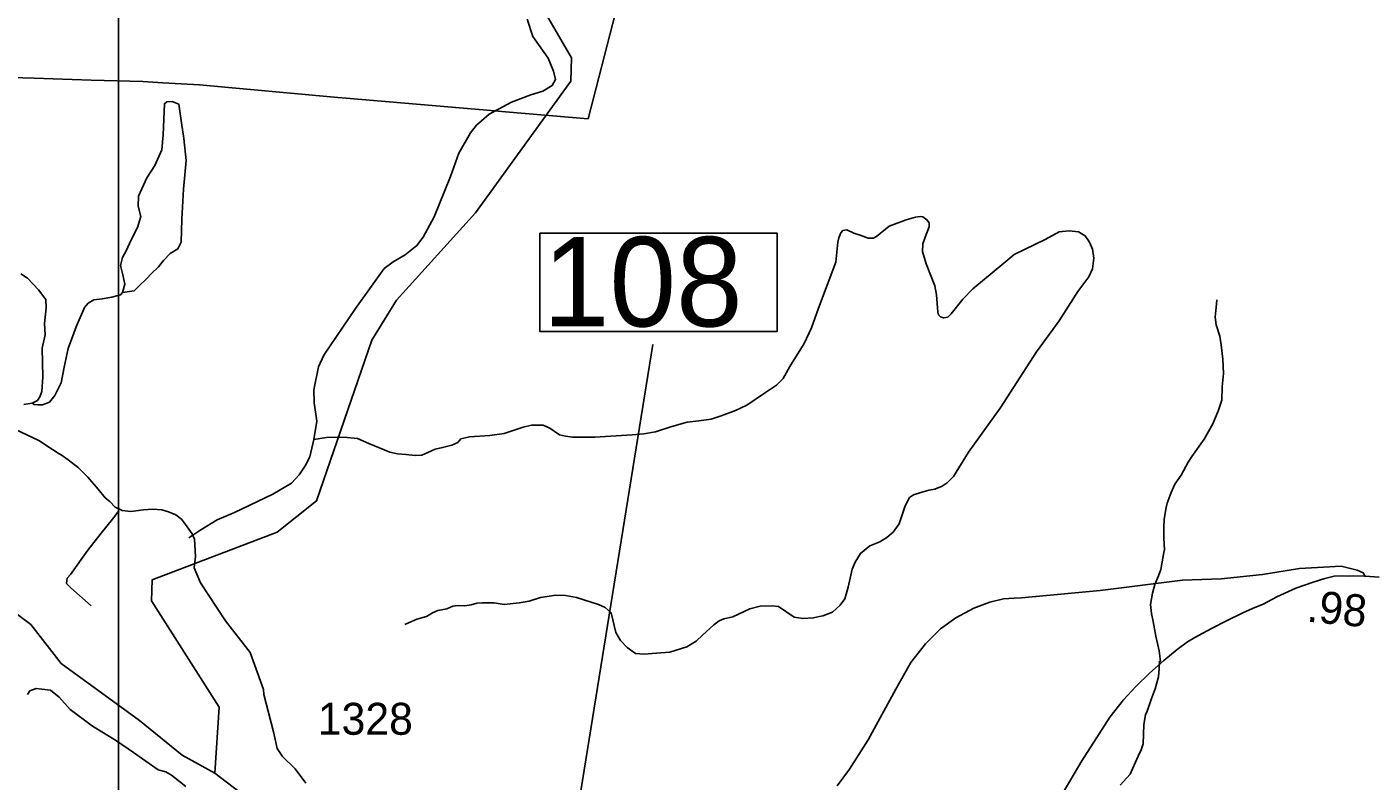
# Model space of a CAD drawing. Extents: x 1159738 to 1321356, y 736314 to 882035.
# Drawn here: x 1193750 to 1199006, y 794392 to 797342 of the extents above; entities that cross this region are included whole.
import ezdxf

# ---------------------------------------------------------------- set-up
doc = ezdxf.new("R2010")
doc.units = 0
for name, color, linetype in [('Exist Boundary Land Use Forest National US Forest Service', 7, 'Continuous'), ('Exist Hydrographic Creek Single Shore', 7, 'Continuous'), ('Exist Hydrographic Misc Water Feature', 7, 'Continuous'), ('Exist Road Non-System Type 51', 7, 'Continuous'), ('Exist Road Secondary Mileage Hundredths English Label', 7, 'Continuous'), ('Exist Road Secondary Structure Standard Bridge Number Label', 7, 'Continuous'), ('Exist Road Secondary Type 51 Attributed', 7, 'Continuous'), ('Exist Road Secondary Type 51 Number Label', 7, 'Continuous'), ('Map Preparation Inset Cut Line', 7, 'Continuous')]:
    doc.layers.add(name, color=color, linetype=linetype)

msp = doc.modelspace()

# ---------------------------------------------------------------- linework, layer by layer
at = {"layer": 'Exist Boundary Land Use Forest National US Forest Service'}
msp.add_lwpolyline([(1192585.3, 797430.1), (1192612.2, 797313), (1192647.2, 797232), (1192653.7, 797233.3), (1193021.2, 797300.1), (1193010.2, 797169), (1193647.2, 797145), (1193779.1, 797141.1), (1194001.2, 797134.2), (1194203.2, 797128.1), (1194281.5, 797123.9), (1194425.2, 797116.1), (1194966.2, 797066.1), (1194997.9, 797063.4), (1195564, 797015.4), (1195620.9, 797010.6), (1195944.2, 796983.1), (1196050.9, 797392.4)], dxfattribs=at)
at = {"layer": 'Exist Hydrographic Creek Single Shore'}
for points in [[(1194484.5, 794422.7), (1194357.3, 794493.7), (1194190.6, 794629.1), (1193884.5, 794851.8), (1193765.6, 795004.1), (1193490.4, 795210.8), (1192957.3, 795566.1), (1192625.5, 795869), (1192523.3, 795985.9), (1192473.4, 796106.5), (1192442.1, 796256.8), (1192425.4, 796573.4), (1192435.9, 796991.7), (1192331.6, 797465.5)], [(1195714.1, 793076.8), (1195497.6, 793416), (1195364.1, 793411.8), (1195249.4, 793449.3), (1195113.8, 793587.1), (1194965.8, 793828.8), (1194927.4, 794085.7), (1194484.5, 794422.7)]]:
    msp.add_lwpolyline(points, dxfattribs=at)
at = {"layer": 'Exist Hydrographic Misc Water Feature'}
for points in [[(1194484.5, 794422.7), (1194501.4, 794681.8), (1194237.4, 795097.4), (1194239.3, 795179.4), (1194728.4, 795366.5), (1194882.4, 795488.2), (1195099.3, 796117.4), (1195195.3, 796273.1), (1195504.3, 796614.8), (1195877.3, 797129.3), (1195879.3, 797221.1), (1195712.3, 797510)], [(1198402.3, 796275.2), (1198401.9, 796257.2), (1198399.2, 796233.2), (1198396.6, 796207.3), (1198399.7, 796177.2), (1198414.6, 796132.7), (1198419.6, 796098.6), (1198426.1, 796042.3), (1198428.6, 795986.2), (1198423.2, 795934.3), (1198421.8, 795882.4), (1198408.8, 795842.7), (1198387.2, 795789.2), (1198353.6, 795730.1), (1198305.7, 795661.3), (1198291.2, 795639.8), (1198263.8, 795588.4), (1198238.8, 795553.1), (1198223.9, 795521.4), (1198208.7, 795479.9), (1198204.2, 795461.9), (1198197, 795416.2), (1198196.1, 795384.1), (1198195, 795342.1), (1198197.9, 795298), (1198195.5, 795286), (1198183.7, 795220.4), (1198175, 795194.5), (1198160.1, 795160.9), (1198151.2, 795127.2), (1198144, 795083.3), (1198147, 795047.3), (1198154.3, 795017), (1198164.6, 794958.7), (1198177.1, 794902.3), (1198182, 794860.2), (1198178, 794860.3), (1198177.3, 794832.2), (1198174.4, 794800.3), (1198161.2, 794752.7), (1198146, 794711), (1198130.8, 794665.4), (1198124.3, 794651.6), (1198117.3, 794613.7), (1198115.2, 794537.7), (1198106.6, 794514), (1198095.8, 794490.2), (1198064.1, 794419), (1198024.8, 794376.1)]]:
    msp.add_lwpolyline(points, dxfattribs=at)
at = {"layer": 'Exist Road Non-System Type 51'}
for points in [[(1195508.3, 796958.3), (1195557.5, 797001.3), (1195644.6, 797047.8), (1195720.1, 797076.9), (1195768.1, 797091.4), (1195804.4, 797113.2), (1195817.4, 797136.5), (1195808.7, 797168.5), (1195788.4, 797219.3), (1195728.8, 797305.1), (1195705.6, 797371.9)], [(1193771, 795870), (1193778.6, 795865.7), (1193793.2, 795863.5), (1193811.1, 795863.5), (1193838, 795874.7), (1193859.3, 795900.5), (1193883.9, 795949.8), (1193896.3, 796011.5), (1193911.9, 796084.4), (1193943.3, 796168.4), (1193975.8, 796244.7), (1193990, 796262), (1194011.3, 796274.3), (1194044.9, 796278.8), (1194081.9, 796285.5), (1194116.6, 796294.5), (1194123.4, 796303.5), (1194133.5, 796336), (1194125.6, 796371.9), (1194115.5, 796408.9), (1194124.5, 796440.3), (1194139.1, 796468.3), (1194157, 796506.4), (1194182.8, 796558), (1194195.1, 796600.6), (1194185, 796641), (1194186.1, 796680.2), (1194218.5, 796752.3), (1194249.9, 796800.6), (1194277.9, 796861.1), (1194283.5, 796919.4), (1194288, 797041.6), (1194297, 797049.5), (1194318.2, 797050.6), (1194344, 797039.4), (1194354.1, 796966.5), (1194364.2, 796905.9), (1194373.1, 796819.6), (1194361.9, 796707.5), (1194356.3, 796589.8), (1194353, 796500.6), (1194340.7, 796473.7), (1194310.4, 796455.8), (1194284.6, 796428.8), (1194264.5, 796404.2), (1194236.5, 796376.1), (1194217.4, 796357.1), (1194187.2, 796327.9), (1194169.2, 796310), (1194123.4, 796303.5)], [(1194383.6, 795344.2), (1194430, 795374.7), (1194493.9, 795413.9), (1194562.2, 795443), (1194711.8, 795514.2), (1194784.4, 795557.8), (1194814.9, 795589.8), (1194838.1, 795624.7), (1194857, 795661), (1194872.4, 795728.3), (1194883.2, 795800.5), (1194873, 795871.7), (1194871.5, 795922.6), (1194890.4, 796012.7), (1194910.5, 796058.2), (1195035.4, 796241.3), (1195147.3, 796396.8), (1195182.1, 796423), (1195228.6, 796450.6), (1195275.1, 796487), (1195299.8, 796520.4), (1195342.7, 796599.3), (1195406.6, 796757.7), (1195438.6, 796847.8), (1195485.1, 796927.7), (1195508.3, 796958.3)], [(1194872.4, 795728.3), (1194921.7, 795736.2), (1194973.3, 795737.3), (1195002.4, 795736.2), (1195042.7, 795731.7), (1195087.5, 795712.6), (1195169.3, 795679), (1195199.6, 795672.3), (1195232.1, 795670), (1195267.9, 795665.5), (1195294.8, 795666.7), (1195317.2, 795677.9), (1195346.4, 795690.2), (1195375.5, 795696.9), (1195411.3, 795705.9), (1195434.9, 795717.1), (1195447.2, 795730.6), (1195480.8, 795738.4), (1195560.4, 795744), (1195616, 795751.9), (1195690, 795776.5), (1195722.5, 795784.4), (1195768.4, 795784.4), (1195795.3, 795773.2), (1195832.3, 795746.3), (1195855.8, 795741.8), (1195883.8, 795737.3), (1195971.2, 795737.3), (1196117, 795746.3), (1196162.9, 795750.8), (1196207.7, 795758.6), (1196271.6, 795778.8), (1196332.1, 795795.6), (1196376.9, 795801.2), (1196426.2, 795807.9), (1196464.3, 795820.3), (1196521.4, 795841.6), (1196565.1, 795862.9), (1196634.6, 795910), (1196681.2, 795940.7), (1196706.9, 795966.5), (1196733.8, 796013.6), (1196788.7, 796103.3), (1196817.9, 796164.9), (1196844.7, 796242.3), (1196913.1, 796421.7), (1196920.9, 796499.6), (1196925.4, 796517.5), (1196932.1, 796536.6), (1196940, 796545.6), (1196955.6, 796547.8), (1196983.7, 796535.5), (1197008.3, 796527.6), (1197039.7, 796516.4), (1197059.8, 796516.4), (1197072.2, 796522), (1197121.5, 796562.4), (1197187.6, 796587), (1197224.5, 796598.2), (1197242.5, 796600.5), (1197253.7, 796599.4), (1197269.4, 796588.2), (1197278.3, 796575.8), (1197278.3, 796560.1), (1197262.6, 796519.8), (1197253.7, 796494), (1197251.4, 796463.7), (1197266, 796415.5), (1197299.6, 796329.2), (1197306.3, 796294.4), (1197310.7, 796243.3), (1197311.8, 796227.6), (1197314.1, 796216.3), (1197321.9, 796208.5), (1197334.2, 796204), (1197351, 796207.4), (1197364.5, 796219.7), (1197409.3, 796276.9), (1197448.5, 796317.3), (1197569.5, 796418.2), (1197610.4, 796451.4), (1197731.4, 796510.9), (1197786.3, 796540), (1197825.5, 796544.5), (1197861.3, 796540), (1197888.2, 796525.4), (1197905, 796500.8), (1197917.3, 796472.8), (1197921.8, 796438), (1197916.2, 796395.4), (1197901.7, 796365.1), (1197859.1, 796306.8), (1197786.3, 796192.4), (1197697.9, 796070.8), (1197555.6, 795851.1), (1197432.4, 795678.8), (1197373.2, 795583.8), (1197348.5, 795559.2), (1197329.5, 795545.7), (1197300.3, 795534.5), (1197276.8, 795530)], [(1193738.5, 795865.5), (1193771, 795870), (1193791.2, 795881.2), (1193801.2, 795894.7), (1193809.1, 795916), (1193812.4, 795973.2), (1193810.2, 796085.3), (1193821.4, 796138), (1193819.2, 796181.7), (1193825.9, 796243.4), (1193824.8, 796275.9), (1193795.6, 796314), (1193753.1, 796358.9), (1193726.2, 796375.7)], [(1197276.8, 795530), (1197245.4, 795521), (1197217.4, 795512.1), (1197201.7, 795500.9), (1197183.8, 795468.3), (1197160.3, 795398.8), (1197137.2, 795365.7), (1197112.6, 795345.6), (1197084.6, 795327.6), (1197046.5, 795313), (1197009.5, 795282.8), (1196988.2, 795249.1), (1196977, 795221.1), (1196961.3, 795150.5), (1196947.9, 795105.6), (1196929.9, 795081), (1196899.7, 795052.9), (1196862.7, 795038.3), (1196825, 795030.8), (1196784.7, 795028.6), (1196750, 795033), (1196689.5, 795074.5), (1196663.7, 795077.9), (1196617.8, 795076.8), (1196577.4, 795065.6), (1196510.2, 795035.3), (1196475.5, 795026.3), (1196456.4, 795019.6), (1196436.3, 795002.8), (1196391.4, 794962.4), (1196366.8, 794940), (1196330.9, 794917.6), (1196263.7, 794896.3), (1196212.2, 794892.9), (1196161.8, 794888.4), (1196130.4, 794891.8), (1196096.8, 794915.3), (1196071, 794942.2), (1196053.1, 794973.6), (1196034, 795049.9), (1196011.6, 795071.2), (1195984.7, 795082.4), (1195898.5, 795110.4), (1195856.6, 795118.1), (1195818.5, 795119.3), (1195758, 795110.3)], [(1194109.2, 795448.7), (1194084.5, 795416.8), (1194040.9, 795361.5), (1193988.7, 795296.1), (1193920.4, 795200.2), (1193907.3, 795185.7), (1193904.4, 795165.3), (1193921.8, 795147.9), (1194001.7, 795078.1)], [(1196918.6, 794374.2), (1196966.4, 794439.4), (1197039.7, 794553.7), (1197148.3, 794751.5), (1197206.9, 794855.8), (1197263.4, 794929.7), (1197321.8, 794987.7), (1197382.6, 795031.1), (1197452.1, 795068.1), (1197515, 795092), (1197569.3, 795105), (1197610.6, 795107.2), (1197638.8, 795109.4), (1197946.9, 795137.4), (1198268.3, 795178.7), (1198420.3, 795183.1), (1198581, 795200.4), (1198726.5, 795224.3), (1198819.3, 795228.6), (1198888.8, 795232.9), (1198951.3, 795217.4), (1198975.2, 795206.6), (1198983.9, 795191.4)], [(1195758, 795110.3), (1195714.3, 795095.7), (1195675.1, 795089), (1195615.7, 795083.4), (1195577.6, 795089), (1195530.6, 795090.1), (1195509.3, 795087.9), (1195486.9, 795081.1), (1195462.2, 795077.8), (1195436.4, 795078.9), (1195415.2, 795076.7), (1195391.6, 795066.6), (1195356.9, 795059.8), (1195335.6, 795049.8), (1195312.1, 795036.3), (1195275.1, 795025.1), (1195228, 795004.9)], [(1194371.2, 794370.5), (1194316, 794415.5), (1194292.8, 794428.6), (1194263.7, 794435.9), (1194166.4, 794504.2), (1194099.9, 794550.1), (1194049.1, 794580.6), (1194007, 794606.8), (1193919.8, 794672.2), (1193876.2, 794720.2), (1193842.8, 794747.8), (1193808, 794752.1), (1193786.2, 794755), (1193762.1, 794745.9), (1193751.9, 794731.4)]]:
    msp.add_lwpolyline(points, dxfattribs=at)
at = {"layer": 'Exist Road Secondary Structure Standard Bridge Number Label'}
msp.add_line((1195733.4, 793226.6), (1196197.5, 796099.8), dxfattribs=at)
msp.add_lwpolyline([(1195755.1, 796535), (1196684.1, 796535), (1196684.1, 796150.9), (1195755.1, 796150.9)], close=True, dxfattribs=at)
at = {"layer": 'Exist Road Secondary Type 51 Attributed'}
for points in [[(1193705.7, 795767.8), (1193796.7, 795724.1), (1193850, 795689.4), (1193875.7, 795672.5), (1193883.6, 795668.2), (1193912, 795649.1), (1193951.7, 795617.3), (1193988.2, 795580.8), (1194029, 795534), (1194056.4, 795499.7), (1194074.1, 795485.5), (1194094.7, 795464.1), (1194114.8, 795454.7), (1194122.5, 795451.1), (1194156.5, 795446.5), (1194205.7, 795452.9), (1194242.2, 795456.1), (1194277.1, 795452.9), (1194304.1, 795444.9), (1194332.7, 795433.8), (1194354.9, 795416.3), (1194370.8, 795395.7), (1194396.2, 795359.2), (1194405.7, 795338.5), (1194407.3, 795316.3), (1194408.9, 795270.2), (1194404.2, 795226.3), (1194429, 795168.3), (1194527.3, 795019.3), (1194622.5, 794895.7), (1194675.4, 794750.9), (1194676.1, 794730.9), (1194714.3, 794585), (1194728.1, 794520.3), (1194749.5, 794487.9), (1194798.9, 794440.2), (1194841.3, 794383.7)], [(1197797.8, 794341.5), (1197874.5, 794471.8), (1197942.1, 794577.4), (1197984.4, 794642.2), (1198037.8, 794709.8), (1198085.7, 794761.9), (1198139.9, 794814.7), (1198196.2, 794864), (1198248.3, 794906.3), (1198287.7, 794937.3), (1198317.3, 794954.2), (1198348.3, 794971.1), (1198384.9, 794990.8), (1198441.2, 795018.9), (1198504, 795050.9), (1198542.5, 795067.5), (1198584.1, 795084.4), (1198637.6, 795112.6), (1198712.2, 795146.4), (1198779.7, 795170.3), (1198824.8, 795184.4), (1198861.4, 795194.3), (1198892.4, 795195.7), (1198914.2, 795193.6), (1198936.7, 795195), (1198983.2, 795193.6), (1199038.1, 795189.4)]]:
    msp.add_lwpolyline(points, dxfattribs=at)
at = {"layer": 'Map Preparation Inset Cut Line'}
msp.add_lwpolyline([(1213574.8, 778108.9), (1194107.7, 778108.9), (1194107.7, 805981), (1213574.8, 805981)], close=True, dxfattribs=at)

# ---------------------------------------------------------------- texts
at = {"layer": 'Exist Road Secondary Mileage Hundredths English Label'}
msp.add_text('.98', height=125, rotation=354.4716, dxfattribs=at).set_placement((1198751.8, 795016.3))
at = {"layer": 'Exist Road Secondary Structure Standard Bridge Number Label'}
msp.add_text('108', height=350, dxfattribs=at).set_placement((1195767.7, 796170.6))
at = {"layer": 'Exist Road Secondary Type 51 Number Label'}
msp.add_text('1328', height=125, dxfattribs=at).set_placement((1194887.5, 794573.4))

doc.saveas('drawing.dxf')
